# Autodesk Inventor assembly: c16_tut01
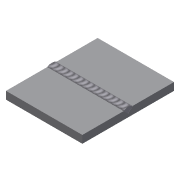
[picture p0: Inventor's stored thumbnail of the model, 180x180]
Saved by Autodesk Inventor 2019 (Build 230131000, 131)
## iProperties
Created: 2010-05
Part Number: c16_tut01
Document SubType Name: Weldment
Designer: CADSoft
Weld Material: Welded Aluminum-6061
Author: CADSoft
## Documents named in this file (2)
- E:\_Deepak\Inventor\Projects\Autodesk Inventor_2019_Project\Resources\Inventor_2018_tut\c16_Inv_2019_tut\c16_Inv_tut_2019\c16_tut01\c16_tut01.iam
- E:\_Deepak\Inventor\Projects\Autodesk Inventor_2019_Project\Resources\Inventor_2018_tut\c16_Inv_2019_tut\c16_Inv_tut_2019\c16_tut01\Plate.ipt
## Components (2 placed, 1 different names)
1. Plate:1 — Mate:1, Flush:1, Flush:2
2. Plate:2 — Mate:1, Flush:1, Flush:2
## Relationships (3: Flush 2, Mate 1)
- Mate:1: Plate:1 ↔ Plate:2
- Flush:1: Plate:1 ↔ Plate:2
- Flush:2: Plate:1 ↔ Plate:2
